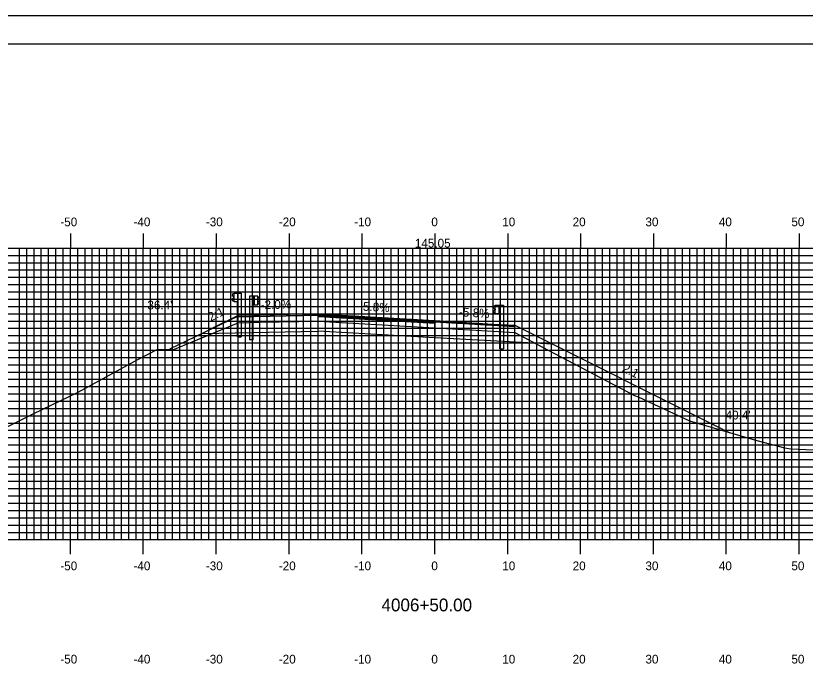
# Model space of a CAD drawing. Extents: x 851360 to 851703, y 364661 to 364881.
# Drawn here: x 851468.2 to 851576.6, y 364791.9 to 364881.3 of the extents above; entities that cross this region are included whole.
import ezdxf

# ---------------------------------------------------------------- set-up
doc = ezdxf.new("R2010")
doc.units = 0
for name, color, linetype in [('ANNOTATION', 7, 'Continuous'), ('BORDER', 7, 'Continuous'), ('D_Guardrail_Beam_Lt', 7, 'Continuous'), ('D_Guardrail_Beam_Rt', 7, 'Continuous'), ('D_Roadway_Centerline_Text', 7, 'Continuous'), ('D_Roadway_Edge_Shoulder', 7, 'Continuous'), ('D_Roadway_Edge_TW', 7, 'Continuous'), ('D_Roadway_Pavement', 7, 'Continuous'), ('D_Roadway_SlopeLines', 7, 'Continuous'), ('D_Roadway_SubGrade', 7, 'Continuous'), ('D_Text_Standard', 7, 'Continuous'), ('H_V ANNOTATION', 7, 'Continuous'), ('M_Guardrail', 7, 'Continuous'), ('M_Roadway_Centerline', 7, 'Continuous'), ('MAJOR', 7, 'Continuous'), ('MINOR', 7, 'Continuous'), ('PLOT BOUNDARY', 7, 'Continuous'), ('S_Roadway_Centerline', 7, 'Continuous')]:
    doc.layers.add(name, color=color, linetype=linetype)

msp = doc.modelspace()

# ---------------------------------------------------------------- linework, layer by layer
at = {"layer": 'BORDER'}
msp.add_lwpolyline([(851376.13, 364667.37), (851696.13, 364667.37), (851696.13, 364877.37), (851376.13, 364877.37)], close=True, dxfattribs=at)
at = {"layer": 'D_Guardrail_Beam_Lt'}
for p, q in [((851500.3, 364842.77), (851500.3, 364836.77)), ((851500.77, 364842.77), (851500.3, 364842.77)), ((851501.46, 364842.77), (851500.77, 364842.77)), ((851500.77, 364842.77), (851500.77, 364841.6)), ((851500.83, 364842.77), (851500.83, 364841.6)), ((851500.94, 364842.77), (851500.94, 364841.6)), ((851501.46, 364841.6), (851501.46, 364842.77)), ((851501.46, 364842.69), (851501.53, 364842.67)), ((851501.69, 364842.42), (851501.5, 364842.28)), ((851501.55, 364842.66), (851501.69, 364842.56)), ((851500.77, 364841.6), (851501.46, 364841.6)), ((851500.79, 364836.77), (851500.79, 364841.6)), ((851501.46, 364842.22), (851501.46, 364842.15)), ((851501.53, 364841.7), (851501.46, 364841.69)), ((851501.5, 364842.09), (851501.69, 364841.95)), ((851501.69, 364841.81), (851501.55, 364841.71)), ((851500.79, 364836.77), (851500.3, 364836.77))]:
    msp.add_line(p, q, dxfattribs=at)
for centre, major_axis, start_param, end_param in [((851501.54, 364842.22), (-0.0789, 0), 5.323254, 6.283185), ((851501.52, 364842.63), (0.0417, 0), 0.959931, 1.376053), ((851501.64, 364842.49), (0.0877, 0), 5.323254, 7.243116), ((851501.54, 364842.15), (-0.0789, 0), 6.283185, 7.243116), ((851501.52, 364841.74), (0.0417, 0), 4.907132, 5.323254), ((851501.64, 364841.88), (0.0877, 0), 5.323254, 7.243116)]:
    msp.add_ellipse(centre, major_axis=major_axis, ratio=0.995501, start_param=start_param, end_param=end_param, dxfattribs=at)
at = {"layer": 'D_Guardrail_Beam_Rt'}
for p, q in [((851533.91, 364841.43), (851533.77, 364841.33)), ((851533.77, 364841.19), (851533.96, 364841.05)), ((851534, 364841.45), (851533.93, 364841.44)), ((851534, 364841.54), (851534.69, 364841.54)), ((851534, 364840.37), (851534, 364841.54)), ((851534.52, 364841.54), (851534.52, 364840.37)), ((851534.62, 364841.54), (851534.62, 364840.37)), ((851534.69, 364841.54), (851535.16, 364841.54)), ((851534.69, 364841.54), (851534.69, 364840.37)), ((851535.16, 364841.54), (851535.16, 364835.54)), ((851533.96, 364840.85), (851533.77, 364840.72)), ((851533.77, 364840.57), (851533.91, 364840.47)), ((851533.93, 364840.47), (851534, 364840.45)), ((851534, 364840.99), (851534, 364840.92)), ((851534.69, 364840.37), (851534, 364840.37)), ((851534.67, 364835.54), (851534.67, 364840.37)), ((851534.67, 364835.54), (851535.16, 364835.54))]:
    msp.add_line(p, q, dxfattribs=at)
for centre, major_axis, start_param, end_param in [((851533.82, 364841.26), (-0.0877, 0), 5.323254, 7.243116), ((851533.93, 364841.4), (-0.0417, 0), 4.907132, 5.323254), ((851533.82, 364840.65), (-0.0877, 0), 5.323254, 7.243116), ((851533.93, 364840.51), (-0.0417, 0), 0.959931, 1.376053), ((851533.92, 364840.99), (0.0789, 0), 0, 0.959931), ((851533.92, 364840.92), (0.0789, 0), 5.323254, 6.283185)]:
    msp.add_ellipse(centre, major_axis=major_axis, ratio=0.995501, start_param=start_param, end_param=end_param, dxfattribs=at)
at = {"layer": 'D_Roadway_Edge_Shoulder'}
for points in [[(851509.73, 364840.35), (851501.73, 364840.19), (851501.73, 364840.19), (851498.73, 364840.13), (851498.73, 364839.96), (851509.73, 364840.15)], [(851525.73, 364839.42), (851533.73, 364838.95), (851533.73, 364838.95), (851536.73, 364838.78), (851536.73, 364838.61), (851525.73, 364839.25)]]:
    msp.add_lwpolyline(points, close=True, dxfattribs=at)
at = {"layer": 'D_Roadway_Edge_TW'}
msp.add_lwpolyline([(851509.73, 364840.35), (851525.73, 364839.42), (851525.73, 364839.25), (851509.73, 364840.15)], close=True, dxfattribs=at)
at = {"layer": 'D_Roadway_Pavement'}
msp.add_lwpolyline([(851509.73, 364840.15), (851525.73, 364839.25), (851525.73, 364839.08), (851509.73, 364839.98)], close=True, dxfattribs=at)
for points in [[(851509.73, 364840.15), (851509.73, 364839.98)], [(851525.73, 364839.25), (851525.73, 364839.08)], [(851525.73, 364839.25), (851525.73, 364839.08)], [(851525.73, 364839.25), (851525.73, 364839.08)]]:
    msp.add_lwpolyline(points, dxfattribs=at)
at = {"layer": 'D_Roadway_SlopeLines'}
msp.add_line((851498.73, 364840.04), (851489.31, 364835.49), dxfattribs=at)
for points in [[(851498.73, 364840.13), (851494.96, 364838.24)], [(851536.73, 364838.78), (851566.12, 364824.09)]]:
    msp.add_lwpolyline(points, dxfattribs=at)
at = {"layer": 'D_Roadway_SubGrade'}
for points in [[(851509.73, 364839.98), (851509.73, 364840.15), (851498.73, 364839.96), (851498.73, 364840.13), (851493.81, 364837.67), (851509.73, 364837.98)], [(851509.73, 364839.98), (851525.73, 364839.08), (851525.73, 364837.08), (851509.73, 364837.98)], [(851525.73, 364839.08), (851525.73, 364839.25), (851536.73, 364838.61), (851536.73, 364838.78), (851541.94, 364836.17), (851525.73, 364837.08)]]:
    msp.add_lwpolyline(points, close=True, dxfattribs=at)
at = {"layer": 'M_Guardrail'}
for p, q in [((851498.08, 364843.09), (851497.93, 364842.99)), ((851497.93, 364842.85), (851498.13, 364842.71)), ((851498.13, 364842.49), (851497.93, 364842.36)), ((851498.18, 364843.11), (851498.09, 364843.1)), ((851498.16, 364842.65), (851498.16, 364842.56)), ((851498.18, 364843.19), (851498.67, 364843.19)), ((851498.18, 364842.02), (851498.18, 364843.19)), ((851498.67, 364843.19), (851499.16, 364843.19)), ((851498.67, 364843.19), (851498.67, 364842.02)), ((851499.16, 364843.19), (851499.16, 364837.19)), ((851497.93, 364842.21), (851498.08, 364842.11)), ((851498.09, 364842.11), (851498.18, 364842.09)), ((851498.67, 364842.02), (851498.18, 364842.02)), ((851498.67, 364837.19), (851498.67, 364842.02)), ((851498.67, 364837.19), (851499.16, 364837.19))]:
    msp.add_line(p, q, dxfattribs=at)
for centre, major_axis, start_param, end_param in [((851497.99, 364842.92), (-0.0877, 0), 5.323254, 7.243116), ((851497.99, 364842.29), (-0.0877, 0), 5.323254, 7.243116), ((851498.1, 364843.06), (-0.0417, 0), 4.886922, 5.323254), ((851498.08, 364842.65), (0.0789, 0), 0, 0.959931), ((851498.08, 364842.56), (0.0789, 0), 5.323254, 6.283185), ((851498.1, 364842.15), (-0.0417, 0), 0.959931, 1.396263)]:
    msp.add_ellipse(centre, major_axis=major_axis, ratio=0.995501, start_param=start_param, end_param=end_param, dxfattribs=at)
at = {"layer": 'MAJOR'}
for p, q in [((851475.73, 364851.37), (851475.73, 364849.37)), ((851485.73, 364851.37), (851485.73, 364849.37)), ((851495.73, 364851.37), (851495.73, 364849.37)), ((851505.73, 364851.37), (851505.73, 364849.37)), ((851515.73, 364851.37), (851515.73, 364849.37)), ((851525.73, 364851.37), (851525.73, 364849.37)), ((851535.73, 364851.37), (851535.73, 364849.37)), ((851545.73, 364851.37), (851545.73, 364849.37)), ((851555.73, 364851.37), (851555.73, 364849.37)), ((851565.73, 364851.37), (851565.73, 364849.37)), ((851575.73, 364851.37), (851575.73, 364849.37)), ((851385.73, 364849.37), (851665.73, 364849.37)), ((851385.73, 364849.37), (851665.73, 364849.37)), ((851475.73, 364809.37), (851475.73, 364849.37)), ((851485.73, 364809.37), (851485.73, 364849.37)), ((851495.73, 364809.37), (851495.73, 364849.37)), ((851505.73, 364809.37), (851505.73, 364849.37)), ((851515.73, 364809.37), (851515.73, 364849.37)), ((851525.73, 364809.37), (851525.73, 364849.37)), ((851535.73, 364809.37), (851535.73, 364849.37)), ((851545.73, 364809.37), (851545.73, 364849.37)), ((851555.73, 364809.37), (851555.73, 364849.37)), ((851565.73, 364809.37), (851565.73, 364849.37)), ((851575.73, 364809.37), (851575.73, 364849.37)), ((851385.73, 364844.37), (851665.73, 364844.37)), ((851385.73, 364839.37), (851665.73, 364839.37)), ((851385.73, 364834.37), (851665.73, 364834.37)), ((851385.73, 364829.37), (851665.73, 364829.37)), ((851385.73, 364824.37), (851665.73, 364824.37)), ((851385.73, 364819.37), (851665.73, 364819.37)), ((851385.73, 364814.37), (851665.73, 364814.37)), ((851385.73, 364809.37), (851665.73, 364809.37)), ((851385.73, 364809.37), (851665.73, 364809.37)), ((851475.73, 364807.37), (851475.73, 364809.37)), ((851485.73, 364807.37), (851485.73, 364809.37)), ((851495.73, 364807.37), (851495.73, 364809.37)), ((851505.73, 364807.37), (851505.73, 364809.37)), ((851515.73, 364807.37), (851515.73, 364809.37)), ((851525.73, 364807.37), (851525.73, 364809.37)), ((851535.73, 364807.37), (851535.73, 364809.37)), ((851545.73, 364807.37), (851545.73, 364809.37)), ((851555.73, 364807.37), (851555.73, 364809.37)), ((851565.73, 364807.37), (851565.73, 364809.37)), ((851575.73, 364807.37), (851575.73, 364809.37))]:
    msp.add_line(p, q, dxfattribs=at)
at = {"layer": 'MINOR'}
for p, q in [((851468.73, 364809.37), (851468.73, 364849.37)), ((851469.73, 364809.37), (851469.73, 364849.37)), ((851470.73, 364809.37), (851470.73, 364849.37)), ((851471.73, 364809.37), (851471.73, 364849.37)), ((851472.73, 364809.37), (851472.73, 364849.37)), ((851473.73, 364809.37), (851473.73, 364849.37)), ((851474.73, 364809.37), (851474.73, 364849.37)), ((851476.73, 364809.37), (851476.73, 364849.37)), ((851477.73, 364809.37), (851477.73, 364849.37)), ((851478.73, 364809.37), (851478.73, 364849.37)), ((851479.73, 364809.37), (851479.73, 364849.37)), ((851480.73, 364809.37), (851480.73, 364849.37)), ((851481.73, 364809.37), (851481.73, 364849.37)), ((851482.73, 364809.37), (851482.73, 364849.37)), ((851483.73, 364809.37), (851483.73, 364849.37)), ((851484.73, 364809.37), (851484.73, 364849.37)), ((851486.73, 364809.37), (851486.73, 364849.37)), ((851487.73, 364809.37), (851487.73, 364849.37)), ((851488.73, 364809.37), (851488.73, 364849.37)), ((851489.73, 364809.37), (851489.73, 364849.37)), ((851490.73, 364809.37), (851490.73, 364849.37)), ((851491.73, 364809.37), (851491.73, 364849.37)), ((851492.73, 364809.37), (851492.73, 364849.37)), ((851493.73, 364809.37), (851493.73, 364849.37)), ((851494.73, 364809.37), (851494.73, 364849.37)), ((851496.73, 364809.37), (851496.73, 364849.37)), ((851497.73, 364809.37), (851497.73, 364849.37)), ((851498.73, 364809.37), (851498.73, 364849.37)), ((851499.73, 364809.37), (851499.73, 364849.37)), ((851500.73, 364809.37), (851500.73, 364849.37)), ((851501.73, 364809.37), (851501.73, 364849.37)), ((851502.73, 364809.37), (851502.73, 364849.37)), ((851503.73, 364809.37), (851503.73, 364849.37)), ((851504.73, 364809.37), (851504.73, 364849.37)), ((851506.73, 364809.37), (851506.73, 364849.37)), ((851507.73, 364809.37), (851507.73, 364849.37)), ((851508.73, 364809.37), (851508.73, 364849.37)), ((851509.73, 364809.37), (851509.73, 364849.37)), ((851510.73, 364809.37), (851510.73, 364849.37)), ((851511.73, 364809.37), (851511.73, 364849.37)), ((851512.73, 364809.37), (851512.73, 364849.37)), ((851513.73, 364809.37), (851513.73, 364849.37)), ((851514.73, 364809.37), (851514.73, 364849.37)), ((851516.73, 364809.37), (851516.73, 364849.37)), ((851517.73, 364809.37), (851517.73, 364849.37)), ((851518.73, 364809.37), (851518.73, 364849.37)), ((851519.73, 364809.37), (851519.73, 364849.37)), ((851520.73, 364809.37), (851520.73, 364849.37)), ((851521.73, 364809.37), (851521.73, 364849.37)), ((851522.73, 364809.37), (851522.73, 364849.37)), ((851523.73, 364809.37), (851523.73, 364849.37)), ((851524.73, 364809.37), (851524.73, 364849.37)), ((851526.73, 364809.37), (851526.73, 364849.37)), ((851527.73, 364809.37), (851527.73, 364849.37)), ((851528.73, 364809.37), (851528.73, 364849.37)), ((851529.73, 364809.37), (851529.73, 364849.37)), ((851530.73, 364809.37), (851530.73, 364849.37)), ((851531.73, 364809.37), (851531.73, 364849.37)), ((851532.73, 364809.37), (851532.73, 364849.37)), ((851533.73, 364809.37), (851533.73, 364849.37)), ((851534.73, 364809.37), (851534.73, 364849.37)), ((851536.73, 364809.37), (851536.73, 364849.37)), ((851537.73, 364809.37), (851537.73, 364849.37)), ((851538.73, 364809.37), (851538.73, 364849.37)), ((851539.73, 364809.37), (851539.73, 364849.37)), ((851540.73, 364809.37), (851540.73, 364849.37)), ((851541.73, 364809.37), (851541.73, 364849.37)), ((851542.73, 364809.37), (851542.73, 364849.37)), ((851543.73, 364809.37), (851543.73, 364849.37)), ((851544.73, 364809.37), (851544.73, 364849.37)), ((851546.73, 364809.37), (851546.73, 364849.37)), ((851547.73, 364809.37), (851547.73, 364849.37)), ((851548.73, 364809.37), (851548.73, 364849.37)), ((851549.73, 364809.37), (851549.73, 364849.37)), ((851550.73, 364809.37), (851550.73, 364849.37)), ((851551.73, 364809.37), (851551.73, 364849.37)), ((851552.73, 364809.37), (851552.73, 364849.37)), ((851553.73, 364809.37), (851553.73, 364849.37)), ((851554.73, 364809.37), (851554.73, 364849.37)), ((851556.73, 364809.37), (851556.73, 364849.37)), ((851557.73, 364809.37), (851557.73, 364849.37)), ((851558.73, 364809.37), (851558.73, 364849.37)), ((851559.73, 364809.37), (851559.73, 364849.37)), ((851560.73, 364809.37), (851560.73, 364849.37)), ((851561.73, 364809.37), (851561.73, 364849.37)), ((851562.73, 364809.37), (851562.73, 364849.37)), ((851563.73, 364809.37), (851563.73, 364849.37)), ((851564.73, 364809.37), (851564.73, 364849.37)), ((851566.73, 364809.37), (851566.73, 364849.37)), ((851567.73, 364809.37), (851567.73, 364849.37)), ((851568.73, 364809.37), (851568.73, 364849.37)), ((851569.73, 364809.37), (851569.73, 364849.37)), ((851570.73, 364809.37), (851570.73, 364849.37)), ((851571.73, 364809.37), (851571.73, 364849.37)), ((851572.73, 364809.37), (851572.73, 364849.37)), ((851573.73, 364809.37), (851573.73, 364849.37)), ((851574.73, 364809.37), (851574.73, 364849.37)), ((851385.73, 364848.37), (851665.73, 364848.37)), ((851385.73, 364847.37), (851665.73, 364847.37)), ((851385.73, 364846.37), (851665.73, 364846.37)), ((851385.73, 364845.37), (851665.73, 364845.37)), ((851385.73, 364843.37), (851665.73, 364843.37)), ((851385.73, 364842.37), (851665.73, 364842.37)), ((851385.73, 364841.37), (851665.73, 364841.37)), ((851385.73, 364840.37), (851665.73, 364840.37)), ((851385.73, 364838.37), (851665.73, 364838.37)), ((851385.73, 364837.37), (851665.73, 364837.37)), ((851385.73, 364836.37), (851665.73, 364836.37)), ((851385.73, 364835.37), (851665.73, 364835.37)), ((851385.73, 364833.37), (851665.73, 364833.37)), ((851385.73, 364832.37), (851665.73, 364832.37)), ((851385.73, 364831.37), (851665.73, 364831.37)), ((851385.73, 364830.37), (851665.73, 364830.37)), ((851385.73, 364828.37), (851665.73, 364828.37)), ((851385.73, 364827.37), (851665.73, 364827.37)), ((851385.73, 364826.37), (851665.73, 364826.37)), ((851385.73, 364825.37), (851665.73, 364825.37)), ((851385.73, 364823.37), (851665.73, 364823.37)), ((851385.73, 364822.37), (851665.73, 364822.37)), ((851385.73, 364821.37), (851665.73, 364821.37)), ((851385.73, 364820.37), (851665.73, 364820.37)), ((851385.73, 364818.37), (851665.73, 364818.37)), ((851385.73, 364817.37), (851665.73, 364817.37)), ((851385.73, 364816.37), (851665.73, 364816.37)), ((851385.73, 364815.37), (851665.73, 364815.37)), ((851385.73, 364813.37), (851665.73, 364813.37)), ((851385.73, 364812.37), (851665.73, 364812.37)), ((851385.73, 364811.37), (851665.73, 364811.37)), ((851385.73, 364810.37), (851665.73, 364810.37))]:
    msp.add_line(p, q, dxfattribs=at)
at = {"layer": 'PLOT BOUNDARY'}
msp.add_lwpolyline([(851359.94, 364661.25), (851699.94, 364661.25), (851699.94, 364881.25), (851359.94, 364881.25)], close=True, dxfattribs=at)
at = {"layer": 'S_Roadway_Centerline'}
for points in [[(851487.64, 364835.46), (851490.03, 364835.5), (851492.43, 364836.5), (851498.73, 364839.13), (851501.73, 364839.19), (851509.73, 364839.35), (851525.73, 364838.42), (851533.73, 364837.96), (851536.73, 364837.78), (851542.07, 364834.97), (851553.14, 364829.15)], [(851385.73, 364816.45), (851390.71, 364816.55), (851395.66, 364816.66), (851407.58, 364817.13), (851418.27, 364817.43), (851423.41, 364817.59), (851424.63, 364817.61), (851436.12, 364818.05), (851441.25, 364818.39), (851448.89, 364819.39), (851457.43, 364820.1), (851470.62, 364826.62), (851476.78, 364829.62), (851484.99, 364834.07), (851487.64, 364835.46)], [(851553.14, 364829.15), (851553.62, 364828.96), (851560.69, 364825.66), (851569.61, 364823.07), (851573.54, 364822), (851574.55, 364821.85), (851576.62, 364821.72), (851587.08, 364821.62), (851593.19, 364822.12), (851603.07, 364822.82), (851609.66, 364823.22), (851613.33, 364823.39), (851615.5, 364823.42), (851626.21, 364824.07), (851627.59, 364824.12), (851631.34, 364824.66), (851643.27, 364826.28), (851655.32, 364827.49), (851660.47, 364827.86), (851665.73, 364827.99)]]:
    msp.add_lwpolyline(points, dxfattribs=at)

# ---------------------------------------------------------------- texts
at = {"layer": 'ANNOTATION'}
for s, rotation, p in [('-2.0%', 1.1458, (851501.84, 364840.99)), ('2:1', 26.5651, (851494.99, 364839.29)), ('5.8%', 356.6806, (851515.84, 364840.79)), ('-5.8%', 356.6806, (851529.02, 364840.03)), ('2:1', 333.4349, (851551.36, 364832.5))]:
    msp.add_text(s, height=1.2, rotation=rotation, dxfattribs=at).set_placement(p)
at = {"layer": 'D_Roadway_Centerline_Text'}
msp.add_text('145.05', height=1.2, dxfattribs=at).set_placement((851522.99, 364849.45))
at = {"layer": 'D_Text_Standard'}
for s, p in [("36.4'", (851486.29, 364840.96)), ("40.4'", (851565.63, 364825.86))]:
    msp.add_text(s, height=1.2, dxfattribs=at).set_placement(p)
at = {"layer": 'H_V ANNOTATION'}
for s, height, p in [('-50', 1.2, (851474.34, 364852.37)), ('-40', 1.2, (851484.38, 364852.37)), ('-30', 1.2, (851494.31, 364852.37)), ('-20', 1.2, (851504.32, 364852.37)), ('-10', 1.2, (851514.66, 364852.37)), ('0', 1.2, (851525.25, 364852.37)), ('10', 1.2, (851534.98, 364852.37)), ('20', 1.2, (851544.64, 364852.37)), ('30', 1.2, (851554.63, 364852.37)), ('40', 1.2, (851564.7, 364852.37)), ('50', 1.2, (851574.66, 364852.37)), ('-50', 1.2, (851474.34, 364805.17)), ('-40', 1.2, (851484.38, 364805.17)), ('-30', 1.2, (851494.31, 364805.17)), ('-20', 1.2, (851504.32, 364805.17)), ('-10', 1.2, (851514.66, 364805.17)), ('0', 1.2, (851525.25, 364805.17)), ('10', 1.2, (851534.98, 364805.17)), ('20', 1.2, (851544.64, 364805.17)), ('30', 1.2, (851554.63, 364805.17)), ('40', 1.2, (851564.7, 364805.17)), ('50', 1.2, (851574.66, 364805.17)), ('4006+50.00', 1.75, (851518.41, 364799.53)), ('-50', 1.2, (851474.34, 364792.37)), ('-40', 1.2, (851484.38, 364792.37)), ('-30', 1.2, (851494.31, 364792.37)), ('-20', 1.2, (851504.32, 364792.37)), ('-10', 1.2, (851514.66, 364792.37)), ('0', 1.2, (851525.25, 364792.37)), ('10', 1.2, (851534.98, 364792.37)), ('20', 1.2, (851544.64, 364792.37)), ('30', 1.2, (851554.63, 364792.37)), ('40', 1.2, (851564.7, 364792.37)), ('50', 1.2, (851574.66, 364792.37))]:
    msp.add_text(s, height=height, dxfattribs=at).set_placement(p)
at = {"layer": 'M_Roadway_Centerline'}
for s, p in [('C', (851513.54, 364838.26)), ('L', (851513.55, 364838.25))]:
    msp.add_text(s, height=0.0146, dxfattribs=at).set_placement(p)

doc.saveas('drawing.dxf')
